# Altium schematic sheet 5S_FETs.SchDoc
size 431 x 279 mm; Date: Not shown in title block; ApprovedBy: Not shown in title block; CheckedBy: Not shown in title block; Author: Not shown in title block; CompanyName: Not shown in title block; Engineer: Not shown in title block; Organization: Not shown in title block; Address1: Not shown in title block; Address2: Not shown in title block; Address3: Not shown in title block; Address4: Not shown in title block; DocumentNumber: 3; Revision: Use project parameter SCH_Rev; SheetNumber: 3; SheetTotal: 5; PageSetup: Record=PageOptions¦CenterHorizontal=True¦CenterVertical=True¦PrintScale=0.64¦XCorrection=1.00¦YCorrection=1.00¦PrintKind=0¦BorderSize=5000000¦LeftOffset=0¦BottomOffset=0¦Orientation=2¦PaperLength=1000¦PaperWidth=1000¦Scale=100¦PaperSource=15¦PrintQuality=600¦MediaType=1¦DitherType=10¦PrintScaleMode=1¦PaperKind=Letter
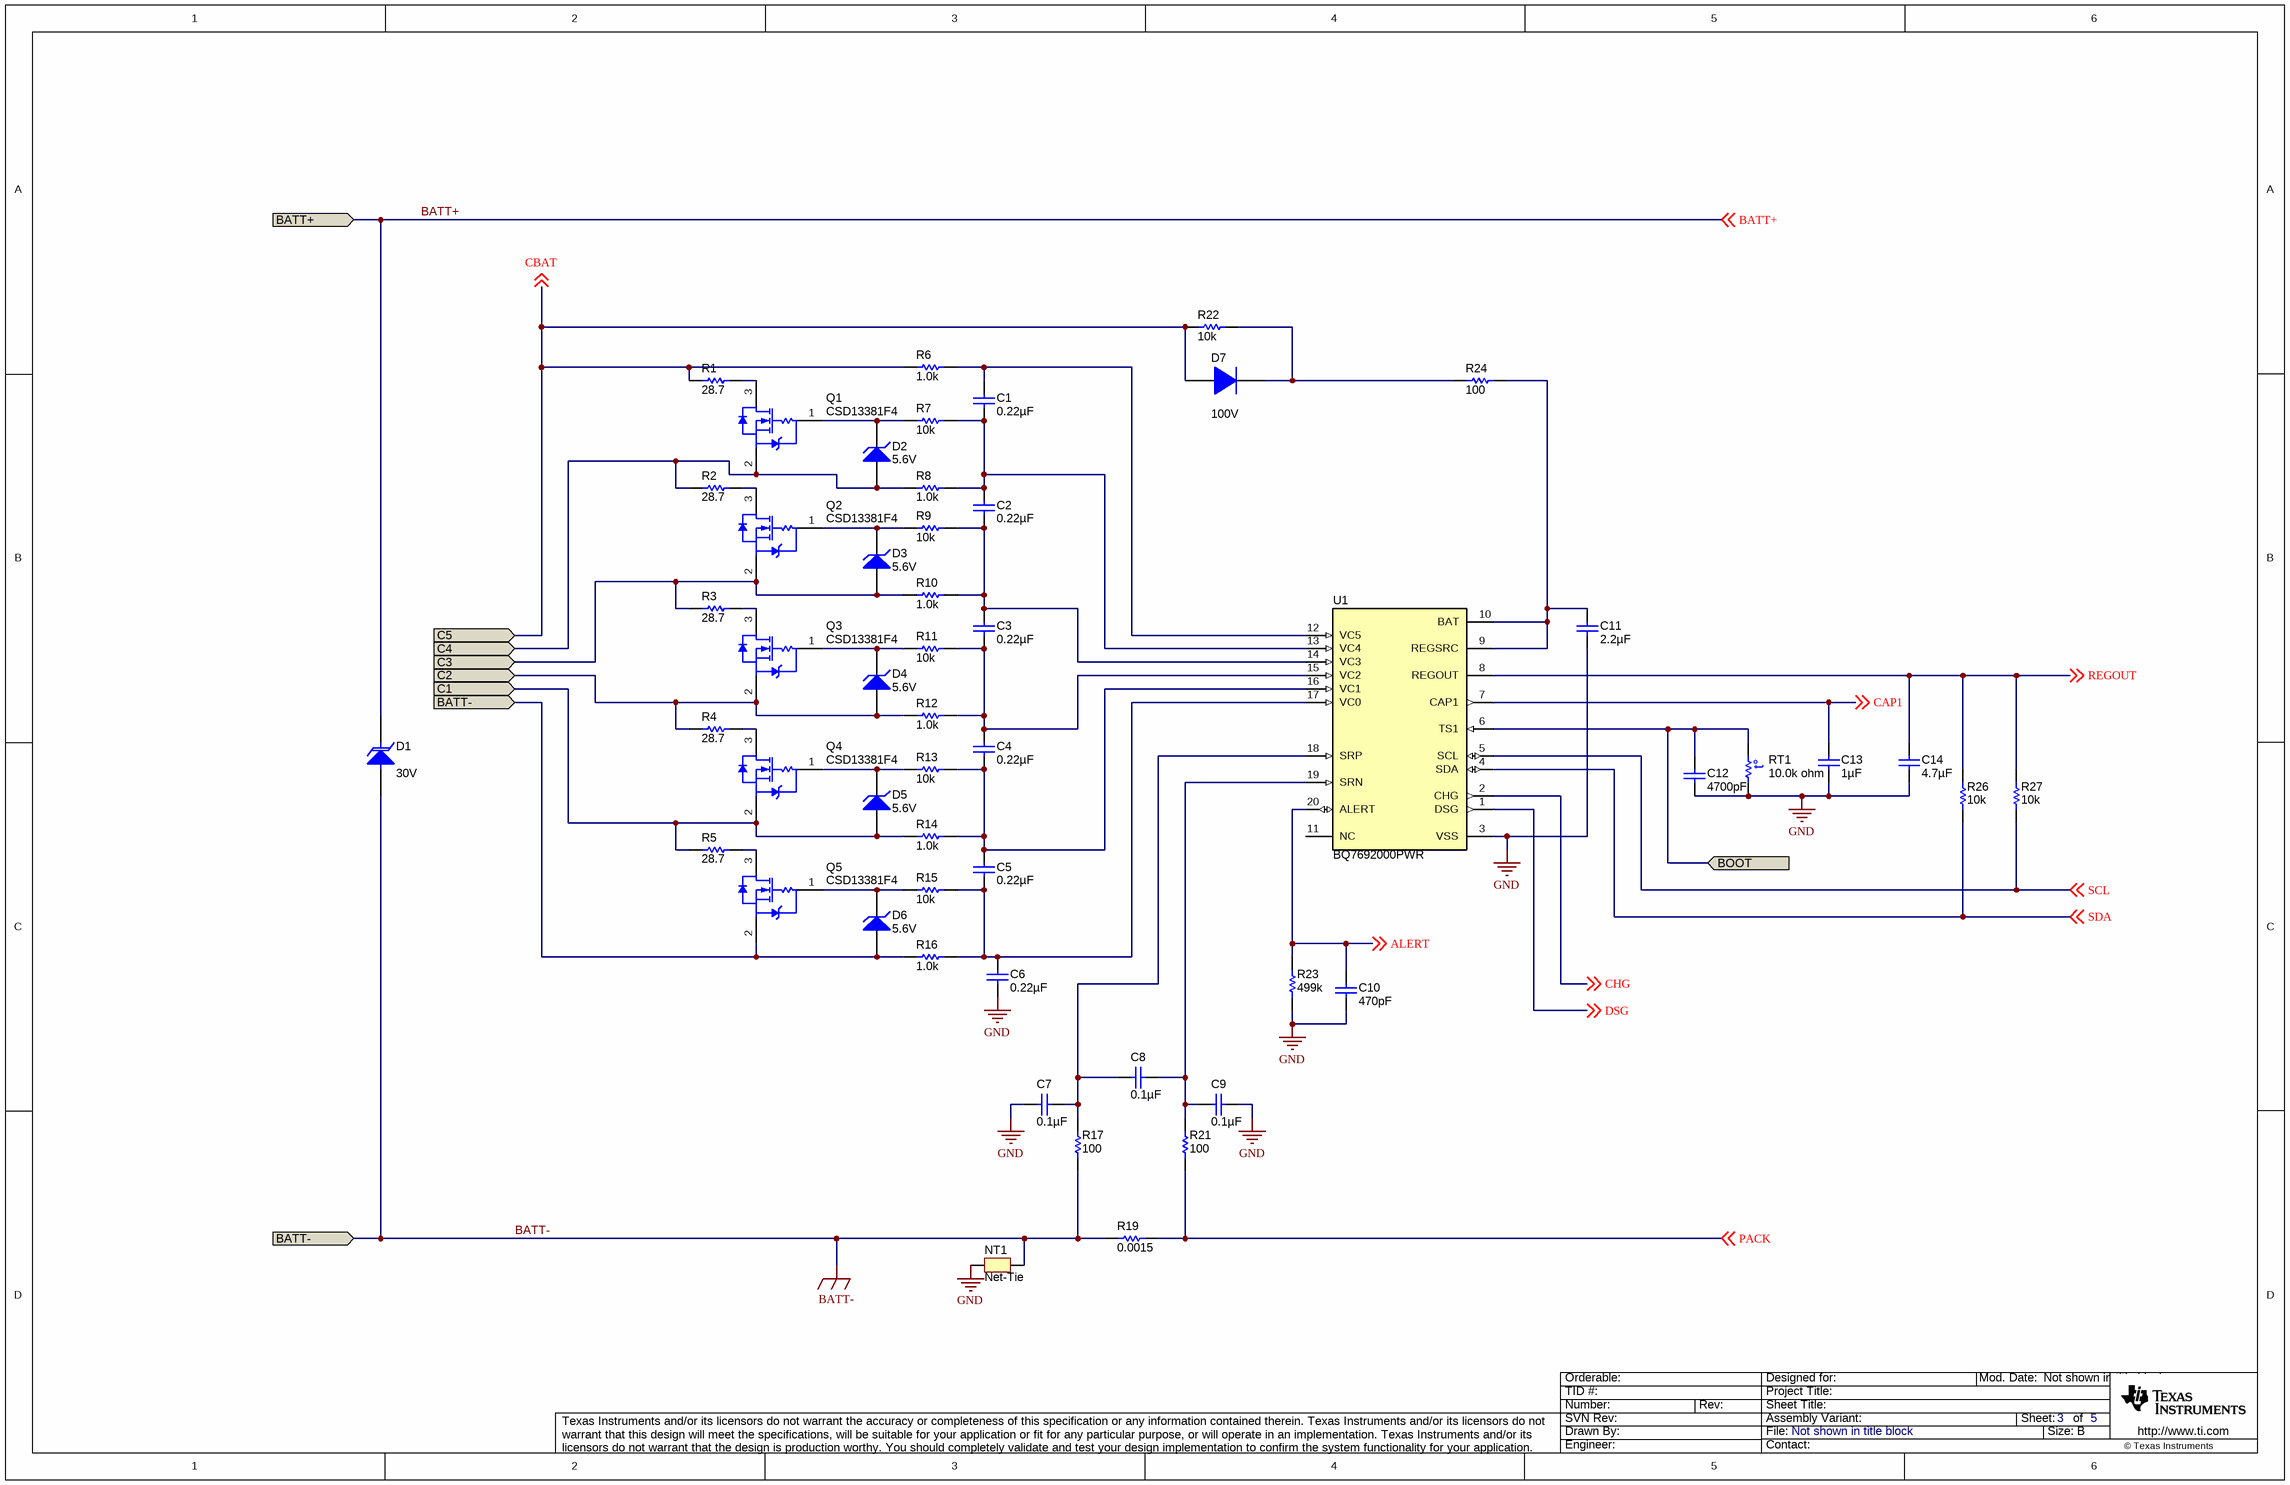
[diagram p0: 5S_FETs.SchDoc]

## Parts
C1  ValueDisplayed: 0.22µF  [0603_095]  (hidden comment: 885012206048)
C2  ValueDisplayed: 0.22µF  [0603_095]  (hidden comment: 885012206048)
C3  ValueDisplayed: 0.22µF  [0603_095]  (hidden comment: 885012206048)
C4  ValueDisplayed: 0.22µF  [0603_095]  (hidden comment: 885012206048)
C5  ValueDisplayed: 0.22µF  [0603_095]  (hidden comment: 885012206048)
C6  ValueDisplayed: 0.22µF  [0603_095]  (hidden comment: 885012206048)
C7  ValueDisplayed: 0.1µF  [0603_095]  (hidden comment: 885012206095)
C8  ValueDisplayed: 0.1µF  [0603_095]  (hidden comment: 885012206095)
C9  ValueDisplayed: 0.1µF  [0603_095]  (hidden comment: 885012206095)
C10  ValueDisplayed: 470pF  [0603_095]  (hidden comment: 885012206081)
C11  ValueDisplayed: 2.2µF  [1206_180]  (hidden comment: GRM31CR61H225KA88L)
C12  ValueDisplayed: 4700pF  [0603_095]  (hidden comment: 885012206087)
C13  ValueDisplayed: 1µF  [0603_095]  (hidden comment: 885012206052)
C14  ValueDisplayed: 4.7µF  [0805_145]  (hidden comment: 885012207025)
D1  value 30V  [SMC]  (hidden comment: SMCJ30A)
D2  value 5.6V  [sod-323]  (hidden comment: MMSZ5232BS-7-F)
D3  value 5.6V  [sod-323]  (hidden comment: MMSZ5232BS-7-F)
D4  value 5.6V  [sod-323]  (hidden comment: MMSZ5232BS-7-F)
D5  value 5.6V  [sod-323]  (hidden comment: MMSZ5232BS-7-F)
D6  value 5.6V  [sod-323]  (hidden comment: MMSZ5232BS-7-F)
D7  value 100V  [SOD-123]  (hidden comment: 1N4148W-7-F)
NT1  Net-Tie  [Net-Tie_10mil]  (net tie, no BOM)
Q1  CSD13381F4  [YJC0003A]
Q2  CSD13381F4  [YJC0003A]
Q3  CSD13381F4  [YJC0003A]
Q4  CSD13381F4  [YJC0003A]
Q5  CSD13381F4  [YJC0003A]
R1  ValueDisplayed: 28.7  [2010]  (hidden comment: CRCW201028R7FKEF)
R2  ValueDisplayed: 28.7  [2010]  (hidden comment: CRCW201028R7FKEF)
R3  ValueDisplayed: 28.7  [2010]  (hidden comment: CRCW201028R7FKEF)
R4  ValueDisplayed: 28.7  [2010]  (hidden comment: CRCW201028R7FKEF)
R5  ValueDisplayed: 28.7  [2010]  (hidden comment: CRCW201028R7FKEF)
R6  ValueDisplayed: 1.0k  [0603]  (hidden comment: CRCW06031K00JNEA)
R7  ValueDisplayed: 10k  [0603]  (hidden comment: CRCW060310K0JNEA)
R8  ValueDisplayed: 1.0k  [0603]  (hidden comment: CRCW06031K00JNEA)
R9  ValueDisplayed: 10k  [0603]  (hidden comment: CRCW060310K0JNEA)
R10  ValueDisplayed: 1.0k  [0603]  (hidden comment: CRCW06031K00JNEA)
R11  ValueDisplayed: 10k  [0603]  (hidden comment: CRCW060310K0JNEA)
R12  ValueDisplayed: 1.0k  [0603]  (hidden comment: CRCW06031K00JNEA)
R13  ValueDisplayed: 10k  [0603]  (hidden comment: CRCW060310K0JNEA)
R14  ValueDisplayed: 1.0k  [0603]  (hidden comment: CRCW06031K00JNEA)
R15  ValueDisplayed: 10k  [0603]  (hidden comment: CRCW060310K0JNEA)
R16  ValueDisplayed: 1.0k  [0603]  (hidden comment: CRCW06031K00JNEA)
R17  value 100  [0805_HV]  (hidden comment: CRCW0805100RFKEA)
R19  ValueDisplayed: 0.0015  [ULRB22512_085]  (hidden comment: ULRB22512R0015FLFSLT)
R21  value 100  [0805_HV]  (hidden comment: CRCW0805100RFKEA)
R22  ValueDisplayed: 10k  [0603]  (hidden comment: CRCW060310K0JNEA)
R23  ValueDisplayed: 499k  [0603]  (hidden comment: CRCW0603499KFKEA)
R24  ValueDisplayed: 100  [1206]  (hidden comment: CRCW1206100RFKEA)
R26  ValueDisplayed: 10k  [0603]  (hidden comment: CRCW060310K0JNEA)
R27  ValueDisplayed: 10k  [0603]  (hidden comment: CRCW060310K0JNEA)
RT1  value 10.0k ohm  [Thermistor_103AT-2]  (hidden comment: 103AT-2)
U1  BQ7692000PWR  [PW0020A_N]

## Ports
BATT+, BATT-, BOOT, C1, C2, C3, C4, C5

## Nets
BATT-: D1.2(A) D6.2(A) NT1.2 Q5.2(S) R16.1 R17.1 R19.1 ; port BATT-
GND: C6.2 C7.2 C9.1 C10.2 C11.2 C12.2 C13.2 C14.2 NT1.1 R23.1 RT1.1 U1.3(VSS)
ALERT: C10.1 R23.2 U1.20(ALERT) ; off-sheet ALERT
BATT+: D1.1(K) ; off-sheet BATT+, port BATT+
BOOT: C12.1 RT1.2 U1.6(TS1) ; port BOOT
C1: D5.2(A) Q4.2(S) R5.1 R14.1 ; port C1
C2: D4.2(A) Q3.2(S) R4.1 R12.1 ; port C2
C3: D3.2(A) Q2.2(S) R3.1 R10.1 ; port C3
C4: D2.2(A) Q1.2(S) R2.1 R8.1 ; port C4
CAP1: C13.1 U1.7(CAP1) ; off-sheet CAP1
CBAT: D7.2(A) R1.1 R6.1 R22.1 ; off-sheet CBAT, port C5
CHG: U1.2(CHG) ; off-sheet CHG
DSG: U1.1(DSG) ; off-sheet DSG
PACK: R19.2 R21.1 ; off-sheet PACK
REGOUT: C14.1 R26.2 R27.1 U1.8(REGOUT) ; off-sheet REGOUT
SCL: R27.2 U1.5(SCL) ; off-sheet SCL
SDA: R26.1 U1.4(SDA) ; off-sheet SDA
NetC1_1: C1.1 R6.2 U1.12(VC5)
NetC1_2: C1.2 C2.1 R7.2 R8.2 U1.13(VC4)
NetC2_2: C2.2 C3.1 R9.2 R10.2 U1.14(VC3)
NetC3_2: C3.2 C4.1 R11.2 R12.2 U1.15(VC2)
NetC4_2: C4.2 C5.1 R13.2 R14.2 U1.16(VC1)
NetC5_2: C5.2 C6.1 R15.2 R16.2 U1.17(VC0)
NetC7_1: C7.1 C8.2 R17.2 U1.18(SRP)
NetC8_1: C8.1 C9.2 R21.2 U1.19(SRN)
NetC11_1: C11.1 R24.2 U1.9(REGSRC) U1.10(BAT)
NetD2_1: D2.1(K) Q1.1(G) R7.1
NetD3_1: D3.1(K) Q2.1(G) R9.1
NetD4_1: D4.1(K) Q3.1(G) R11.1
NetD5_1: D5.1(K) Q4.1(G) R13.1
NetD6_1: D6.1(K) Q5.1(G) R15.1
NetD7_1: D7.1(K) R22.2 R24.1
NetQ1_3: Q1.3(D) R1.2
NetQ2_3: Q2.3(D) R2.2
NetQ3_3: Q3.3(D) R3.2
NetQ4_3: Q4.3(D) R4.2
NetQ5_3: Q5.3(D) R5.2

Not connected (* = marked no-connect by the designer): U1 11(NC)

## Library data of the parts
C1-C6 = 885012206048: CAP, CERM, 0.22 µF, 16 V, +/- 10%, X7R, 0603_095; Manufacturer: Wurth Elektronik; Polarized: N; CompType: Capacitor; Value: 0.22uF; U/M: EA; Cap_F: 0.00000022; Tolerance_%: 10; Value1: Unknown; VDC_V: 16; Value2: 16V; TaMin_C: -55; TaMax_C: 125; Cap_Case: 0603
C7-C9 = 885012206095: CAP, CERM, 0.1 µF, 50 V, +/- 10%, X7R, 0603_095; Manufacturer: Wurth Elektronik; Polarized: N; CompType: Capacitor; Value: 0.1uF; U/M: EA; Cap_F: 0.0000001; Tolerance_%: 10; Value1: Unknown; VDC_V: 50; Value2: 50V; TaMin_C: -55; TaMax_C: 125; Cap_Case: 0603
C10 = 885012206081: CAP, CERM, 470 pF, 50 V, +/- 10%, X7R, 0603_095; Manufacturer: Wurth Elektronik; Polarized: N; CompType: Capacitor; Value: 470pF; U/M: EA; Cap_F: 0.00000000047; Tolerance_%: 10; Value1: Unknown; VDC_V: 50; Value2: 50V; TaMin_C: -55; TaMax_C: 125; Cap_Case: 0603
C11 = GRM31CR61H225KA88L: CAP, CERM, 2.2 µF, 50 V, +/- 10%, X5R, 1206; Manufacturer: MuRata; Polarized: N; CompType: Capacitor; Value: 2.2uF; U/M: EA; Cap_F: 0.0000022; Tolerance_%: 10; Value1: Unknown; VDC_V: 50; Value2: 50V; TaMin_C: -55; TaMax_C: 85; Cap_Case: 1206; SizeArea_mm2: 5.12; SizeAreaWB_mm2: 10.92; SizeX_mm: 3.2; SizeY_mm: 1.6; SizeZ_mm: 1.8; AEC Category: Q200
C12 = 885012206087: CAP, CERM, 4700 pF, 50 V, +/- 10%, X7R, 0603_095; Manufacturer: Wurth Elektronik; Polarized: N; CompType: Capacitor; Value: 4700pF; U/M: EA; Cap_F: 0.0000000047; Tolerance_%: 10; Value1: Unknown; VDC_V: 50; Value2: 50V; TaMin_C: -55; TaMax_C: 125; Cap_Case: 0603
C13 = 885012206052: CAP, CERM, 1 µF, 16 V, +/- 10%, X7R, 0603_095; Manufacturer: Wurth Elektronik; Polarized: N; CompType: Capacitor; Value: 1uF; U/M: EA; Cap_F: 0.000001; Tolerance_%: 10; Value1: Unknown; VDC_V: 16; Value2: 16V; TaMin_C: -55; TaMax_C: 125; Cap_Case: 0603
C14 = 885012207025: CAP, CERM, 4.7 µF, 10 V, +/- 10%, X7R, 0805; Manufacturer: Wurth Elektronik; Polarized: N; CompType: Capacitor; Value: 4.7uF; U/M: EA; Cap_F: 0.0000047; Tolerance_%: 10; Value1: Unknown; Value2: 10V; TaMin_C: -55; TaMax_C: 125; Cap_Case: 0805
D1 = SMCJ30A: Diode, TVS, Uni, 30 V, SMC; Manufacturer: Fairchild Semiconductor; U/M: EA; Vr_V: 30; Value1: W; SizeAreaWB_mm2: 83.2686; SizeArea_mm2: 50.5686; SizeX_mm: 8.13; SizeY_mm: 6.22; SizeZ_mm: 2.6; AEC Category: Q101
D2-D6 = MMSZ5232BS-7-F: Diode, Zener, 5.6V, 200mW, SOD-323; Manufacturer: Diodes Inc.; U/M: EA; Power_W: 0.2; Vz_V: 5.6; Value1: 0.2W; RJA_CperW: 350
D7 = 1N4148W-7-F: Diode, Ultrafast, 100V, 0.15A, SOD-123; Manufacturer: Diodes Inc.; U/M: EA; Vf_V: 1.25; Value2: 1.25V; Io_A: 0.15; Vr_V: 100; TJmax_C: 150
NT1 = Net-Tie: Single point connection between nets.; SymbolCreator: codlsc
Q1-Q5 = CSD13381F4: MOSFET, N/P-CH, 12 V, 2.1 A, 1.0x0.35x0.6mm; Manufacturer: Texas Instruments; Alternate Manufacturer: None; SymbolCreator: a0411947; U/M: EA; ChType: N; Value: 12V; VdsMax_V: 12; Value1: 0.14 ohm; Rdson45_ohm: 0.14; Value2: 1.06 nC; QgTyp_nC: 1.06; Vgs_V: 8; IdsMax_A: 2.1
R1-R5 = CRCW201028R7FKEF: RES, 28.7, 1%, 0.75 W, 2010; Manufacturer: Vishay-Dale; CompType: Resistor; Value: 28.7; Value_Code: 28R7; Tolerance_%: 1; Power_W: 0.75; Value2: 0.75W; VDC_V: 400; TempCo: 100 ppm/C; EIA_Code: E96; U/M: EA
R6 R8 R10 R12 R14 R16 = CRCW06031K00JNEA: RES, 1.0 k, 5%, 0.1 W, 0603; Manufacturer: Vishay-Dale; CompType: Resistor; Value: 1.0k; Res_ohm: 1000; Value_Code: 1k00; Tolerance_%: 5; Power_W: 0.1; Value2: 0.1W; VDC_V: 75; TempCo: 200 ppm/C; EIA_Code: E24; U/M: EA
R7 R9 R11 R13 R15 R22 R26 R27 = CRCW060310K0JNEA: RES, 10 k, 5%, 0.1 W, 0603; Manufacturer: Vishay-Dale; CompType: Resistor; Value: 10k; Res_ohm: 10000; Value_Code: 10k0; Tolerance_%: 5; Power_W: 0.1; Value2: 0.1W; VDC_V: 75; TempCo: 200 ppm/C; EIA_Code: E24; U/M: EA
R17 R21 = CRCW0805100RFKEA: RES, 100 ohm, 1%, 0.125W, 0805; Manufacturer: Vishay-Dale; CompType: Resistor; Value_Code: 100R; Tolerance_%: 1; Power_W: 0.125; VDC_V: 150; TempCo: 100 ppm/C; EIA_Code: E96; U/M: EA
R19 = ULRB22512R0015FLFSLT: RES, 0.0015, 1%, 2 W, AEC-Q200 Grade 0, 2512; Manufacturer: TT Electronics/IRC; CompType: Resistor; Value: 0.0015; Value_Code: 1L500; Tolerance_%: 1; Power_W: 2; Value2: 2W; TempCo: 50 ppm/C; U/M: EA; AEC Category: Q200; AEC Qualified: Y; AEC Grade: 0
R23 = CRCW0603499KFKEA: RES, 499 k, 1%, 0.1 W, 0603; Manufacturer: Vishay-Dale; CompType: Resistor; Value: 499k; Res_ohm: 499000; Tolerance_%: 1; Power_W: 0.1; Value2: 0.1W; VDC_V: 75; TempCo: 100 ppm/C; EIA_Code: E96; U/M: EA
R24 = CRCW1206100RFKEA: RES, 100, 1%, 0.25 W, 1206; Manufacturer: Vishay-Dale; CompType: Resistor; Value: 100; Value_Code: 100R; Tolerance_%: 1; Power_W: 0.25; Value2: 0.25W; VDC_V: 200; TempCo: 100 ppm/C; SizeArea_mm2: 5.12; SizeX_mm: 3.2; SizeY_mm: 1.6; SizeZ_mm: 1.35; EIA_Code: E96; U/M: EA; AEC Category: Q200
RT1 = 103at-2: Thermistor NTC, 10.0k ohm, 1%, Disc, 5x8.4 mm; Manufacturer: SEMITEC Corporation; Tolerance_%: 1; Power_W: 0.01; TaMin_C: -50; TaMax_C: 110; U/M: EA
U1 = BQ7692000PWR: Battery Monitor for Lithium-Ion and Phosphate Battery Packs, PW0020A (TSSOP-20); Manufacturer: Texas Instruments; SymbolCreator: a0411947; SizeArea_mm2: 43.56; SizeAreaWB_mm2: 73.96; SizeX_mm: 6.6; SizeZ_mm: 1.2; CompType: IC; U/M: EA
